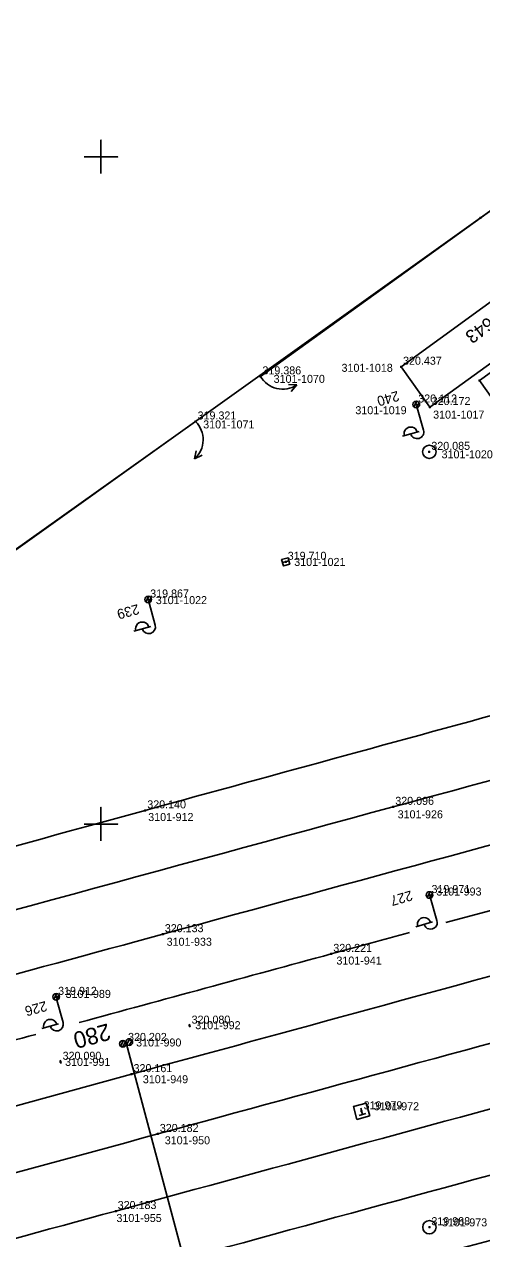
# Model space of a CAD drawing. Extents: x -821875 to -821475, y -1070280 to -1069975.
# Drawn here: x -821655.7 to -821621.5, y -1070181.1 to -1070090.1 of the extents above; entities that cross this region are included whole.
import ezdxf

# ---------------------------------------------------------------- set-up
doc = ezdxf.new("R2010")
doc.units = 0
for name, color, linetype in [('Vrstva 1', 7, 'Continuous'), ('Vrstva 11', 7, 'Continuous'), ('Vrstva 17', 7, 'Continuous'), ('Vrstva 20', 7, 'Continuous'), ('Vrstva 23', 7, 'Continuous'), ('Vrstva 25', 7, 'Continuous'), ('Vrstva 3', 7, 'Continuous'), ('Vrstva 33', 7, 'Continuous'), ('Vrstva 36', 7, 'Continuous'), ('Vrstva 43', 7, 'Continuous'), ('Vrstva 52', 7, 'Continuous'), ('Vrstva 53', 7, 'Continuous'), ('Vrstva 57', 7, 'Continuous'), ('Vrstva 60', 7, 'Continuous'), ('Vrstva 61', 7, 'Continuous')]:
    doc.layers.add(name, color=color, linetype=linetype)

# ---------------------------------------------------------------- blocks, each defined once
blk = doc.blocks.new('BOD')
at = {"layer": 'Vrstva 3'}
for p, q in [((-0.15, 0), (0.15, 0)), ((0, -0.15), (0, 0.15))]:
    blk.add_line(p, q, dxfattribs=at)

msp = doc.modelspace()

# ---------------------------------------------------------------- linework, layer by layer
at = {"layer": 'Vrstva 1'}
msp.add_line((-821601.389, -1070151.191), (-821624.154, -1070157.393), dxfattribs=at)
for points in [[(-821651.25, -1070100), (-821650, -1070100), (-821650, -1070098.75), (-821650, -1070100), (-821648.75, -1070100), (-821650, -1070100), (-821650, -1070101.25)], [(-821651.25, -1070150), (-821650, -1070150), (-821650, -1070148.75), (-821650, -1070150), (-821648.75, -1070150), (-821650, -1070150), (-821650, -1070151.25)], [(-821647.71, -1070168.745), (-821689.454, -1070180.207)]]:
    msp.add_lwpolyline(points, dxfattribs=at)
for points in [[(-821515.135, -1070116.801), (-821528.933, -1070119.148), (-821545.007, -1070122.191), (-821565.452, -1070126.847), (-821593.911, -1070134.524), (-821616.729, -1070140.773), (-821646.681, -1070148.977), (-821681.98, -1070158.691), (-821694.065, -1070162.076), (-821706.535, -1070165.88), (-821718.507, -1070169.937)], [(-821540.596, -1070125.428), (-821552.18, -1070128.307), (-821562.458, -1070130.974), (-821571.2, -1070133.262), (-821591.887, -1070138.848), (-821628.102, -1070148.713), (-821679.285, -1070162.663)], [(-821540.784, -1070127.42), (-821561.358, -1070134.748), (-821573.215, -1070138.464), (-821586.824, -1070142.326), (-821602.341, -1070146.553), (-821645.37, -1070158.257), (-821677.113, -1070166.912)], [(-821500, -1070129.211), (-821517.764, -1070133.43), (-821543.081, -1070140.233), (-821582.867, -1070151.05), (-821612.032, -1070158.997), (-821647.71, -1070168.745)], [(-821500, -1070134.157), (-821525.227, -1070140.424), (-821545.665, -1070145.962), (-821584.89, -1070156.649), (-821608.863, -1070163.173), (-821645.742, -1070173.228), (-821684.141, -1070183.689)], [(-821500, -1070139.002), (-821505.719, -1070140.359), (-821526.796, -1070145.75), (-821547.362, -1070151.333), (-821583.687, -1070161.245), (-821611.332, -1070168.765), (-821648.899, -1070179.006), (-821680.4, -1070187.609), (-821711.133, -1070195.974)], [(-821500, -1070143.947), (-821500.602, -1070144.082), (-821526.98, -1070150.62), (-821544.477, -1070155.432), (-821558.026, -1070159.151), (-821579.135, -1070164.951), (-821610.376, -1070173.463), (-821647.463, -1070183.595), (-821678.921, -1070192.191), (-821710.276, -1070200.761)], [(-821500, -1070148.817), (-821511.77, -1070151.622), (-821530.609, -1070156.564), (-821556.604, -1070163.701), (-821576.895, -1070169.217), (-821607.294, -1070177.525), (-821643.435, -1070187.343), (-821669.656, -1070194.488)], [(-821626.879, -1070158.135), (-821632.745, -1070159.733), (-821651.624, -1070164.877)], [(-821654.889, -1070165.767), (-821663.065, -1070167.996), (-821679.008, -1070172.349)]]:
    msp.add_spline(points, degree=3, dxfattribs=at)
at = {"layer": 'Vrstva 11'}
for p, q in [((-821648.314, -1070166.228), (-821648.548, -1070166.639)), ((-821648.157, -1070166.332), (-821648.379, -1070166.721)), ((-821648.122, -1070166.406), (-821638.674, -1070201.687)), ((-821647.829, -1070166.097), (-821648.065, -1070166.509)), ((-821647.673, -1070166.201), (-821647.894, -1070166.589))]:
    msp.add_line(p, q, dxfattribs=at)
for centre in [(-821648.363, -1070166.472), (-821648.363, -1070166.472), (-821647.881, -1070166.34), (-821647.881, -1070166.34)]:
    msp.add_circle(centre, 0.25, dxfattribs=at)
at = {"layer": 'Vrstva 17'}
for points in [[(-821638.053, -1070116.453), (-821603.288, -1070091.399)], [(-821785.347, -1070191.975), (-821782.414, -1070181.46), (-821781.172, -1070177.336), (-821779.748, -1070173.57), (-821777.608, -1070170.061), (-821774.963, -1070166.997), (-821771.94, -1070164.191), (-821768.526, -1070161.97), (-821763.149, -1070159.284), (-821721.814, -1070148.42), (-821694.32, -1070141.229), (-821660.419, -1070132.27), (-821642.912, -1070119.833)]]:
    msp.add_lwpolyline(points, dxfattribs=at)
at = {"layer": 'Vrstva 20'}
msp.add_lwpolyline([(-821621.64, -1070116.774), (-821619.812, -1070119.329), (-821614.129, -1070115.247), (-821615.939, -1070112.668), (-821621.64, -1070116.774)], dxfattribs=at)
at = {"layer": 'Vrstva 23'}
for p, q in [((-821635.335, -1070117.095), (-821635.944, -1070117.052)), ((-821635.746, -1070117.575), (-821635.335, -1070117.095)), ((-821635.335, -1070117.095), (-821635.746, -1070117.575)), ((-821642.988, -1070122.626), (-821642.873, -1070122.026)), ((-821642.418, -1070122.351), (-821642.988, -1070122.626)), ((-821642.988, -1070122.626), (-821642.418, -1070122.351))]:
    msp.add_line(p, q, dxfattribs=at)
msp.add_lwpolyline([(-821627.52, -1070115.73), (-821618.47, -1070109.17), (-821616.3, -1070112.22), (-821625.37, -1070118.75), (-821627.52, -1070115.73)], dxfattribs=at)
for centre, start, end in [((-821636.392, -1070115.496), 209.9472, 303.46708), ((-821644.263, -1070121.193), 311.68479, 45.20467)]:
    msp.add_arc(centre, 1.917, start, end, dxfattribs=at)
at = {"layer": 'Vrstva 25'}
for p, q in [((-821626.325, -1070118.317), (-821626.557, -1070118.736)), ((-821626.171, -1070118.424), (-821626.384, -1070118.809)), ((-821626.311, -1070118.801), (-821625.83, -1070120.483)), ((-821626.166, -1070120.58), (-821627.417, -1070120.937)), ((-821646.405, -1070132.933), (-821646.643, -1070133.348)), ((-821646.252, -1070133.042), (-821646.47, -1070133.423)), ((-821646.398, -1070133.416), (-821645.94, -1070135.105)), ((-821646.278, -1070135.197), (-821647.532, -1070135.537)), ((-821625.331, -1070155.079), (-821625.562, -1070155.498)), ((-821625.176, -1070155.186), (-821625.388, -1070155.57)), ((-821625.316, -1070155.562), (-821624.831, -1070157.243)), ((-821625.167, -1070157.34), (-821626.416, -1070157.701)), ((-821653.304, -1070162.711), (-821653.542, -1070163.127)), ((-821653.15, -1070162.819), (-821653.369, -1070163.202)), ((-821653.296, -1070163.194), (-821652.836, -1070164.883)), ((-821653.173, -1070164.975), (-821654.428, -1070165.317))]:
    msp.add_line(p, q, dxfattribs=at)
for centre in [(-821626.38, -1070118.56), (-821626.38, -1070118.56), (-821646.463, -1070133.175), (-821646.463, -1070133.175), (-821625.385, -1070155.322), (-821625.385, -1070155.322), (-821653.362, -1070162.953), (-821653.362, -1070162.953)]:
    msp.add_circle(centre, 0.25, dxfattribs=at)
for centre, start, end in [((-821626.793, -1070120.752), 15.25749, 196.66264), ((-821626.311, -1070120.62), 195.96007, 15.96007), ((-821646.906, -1070135.361), 14.46508, 195.87022), ((-821646.422, -1070135.236), 195.16765, 15.16765), ((-821625.793, -1070157.515), 15.38101, 196.78616), ((-821625.311, -1070157.382), 196.08359, 16.08359), ((-821653.802, -1070165.14), 14.54453, 195.94968), ((-821653.318, -1070165.014), 195.24711, 15.24711)]:
    msp.add_arc(centre, 0.5, start, end, dxfattribs=at)
at = {"layer": 'Vrstva 33'}
for p, q in [((-821630.167, -1070171.706), (-821630.65, -1070171.837)), ((-821630.408, -1070171.772), (-821630.54, -1070171.288))]:
    msp.add_line(p, q, dxfattribs=at)
msp.add_lwpolyline([(-821629.86, -1070171.882), (-821630.826, -1070172.144), (-821631.088, -1070171.178), (-821630.122, -1070170.916), (-821629.86, -1070171.882)], dxfattribs=at)
at = {"layer": 'Vrstva 36'}
for p, q in [((-821643.329, -1070165.233), (-821643.394, -1070164.992)), ((-821652.991, -1070167.94), (-821653.058, -1070167.699))]:
    msp.add_line(p, q, dxfattribs=at)
at = {"layer": 'Vrstva 43'}
msp.add_lwpolyline([(-821635.92, -1070130.28), (-821635.854, -1070130.521), (-821636.335, -1070130.654), (-821636.468, -1070130.173), (-821635.987, -1070130.04), (-821635.92, -1070130.28), (-821636.402, -1070130.414)], dxfattribs=at)
for centre in [(-821625.401, -1070122.108), (-821625.397, -1070180.216)]:
    msp.add_circle(centre, 0.5, dxfattribs=at)
at = {"layer": 'Vrstva 52'}
msp.add_lwpolyline([(-821627.52, -1070115.73), (-821618.47, -1070109.17), (-821616.3, -1070112.22), (-821625.37, -1070118.75), (-821627.52, -1070115.73)], dxfattribs=at)
at = {"layer": 'Vrstva 53'}
msp.add_lwpolyline([(-821734.56, -1070151.86), (-821659.89, -1070131.96), (-821621.57, -1070104.56), (-821609.88, -1070096.2), (-821593.26, -1070084.26), (-821583.18, -1070077.05), (-821575.55, -1070071.56), (-821563.91, -1070063.18), (-821553.98, -1070056.16), (-821553.05, -1070055.49), (-821551.21, -1070054.16)], dxfattribs=at)

# ---------------------------------------------------------------- block references
at = {"layer": 'Vrstva 60', "xscale": 0.5, "yscale": 0.5}
for p in [(-821621.57, -1070104.56), (-821627.52, -1070115.73), (-821638.053, -1070116.453), (-821621.64, -1070116.774), (-821626.38, -1070118.56), (-821625.37, -1070118.75), (-821642.912, -1070119.833), (-821625.401, -1070122.108), (-821636.161, -1070130.347), (-821646.463, -1070133.175), (-821646.681, -1070148.977), (-821628.102, -1070148.713), (-821625.385, -1070155.322), (-821645.37, -1070158.257), (-821632.745, -1070159.733), (-821653.362, -1070162.953), (-821643.362, -1070165.111), (-821648.122, -1070166.406), (-821653.025, -1070167.818), (-821647.71, -1070168.745), (-821630.474, -1070171.53), (-821645.742, -1070173.228), (-821648.899, -1070179.006), (-821625.397, -1070180.216)]:
    msp.add_blockref('BOD', p, dxfattribs=at)

# ---------------------------------------------------------------- texts
at = {"layer": 'Vrstva 11'}
msp.add_text('280', height=1.25, rotation=195.30297, dxfattribs=at).set_placement((-821649.49, -1070164.925))
at = {"layer": 'Vrstva 25'}
for s, rotation, p in [('240', 195.96009, (-821627.783, -1070117.532)), ('239', 195.16777, (-821647.252, -1070133.516)), ('227', 196.08371, (-821626.785, -1070154.972)), ('226', 195.24712, (-821654.157, -1070163.261))]:
    msp.add_text(s, height=0.75, rotation=rotation, dxfattribs=at).set_placement(p)
at = {"layer": 'Vrstva 57'}
msp.add_text('5643', height=1, rotation=215.69159, dxfattribs=at).set_placement((-821620.383, -1070111.511))
at = {"layer": 'Vrstva 60'}
for s, p in [('3101-1070', (-821637.065, -1070116.938)), ('3101-1018', (-821631.977, -1070116.111)), ('3101-1019', (-821630.941, -1070119.289)), ('3101-1017', (-821625.116, -1070119.618)), ('3101-1071', (-821642.343, -1070120.353)), ('3101-1020', (-821624.483, -1070122.593)), ('3101-1021', (-821635.522, -1070130.658)), ('3101-1022', (-821645.894, -1070133.521)), ('3101-926', (-821627.775, -1070149.574)), ('3101-912', (-821646.462, -1070149.776)), ('3101-993', (-821624.883, -1070155.361)), ('3101-933', (-821645.081, -1070159.125)), ('3101-941', (-821632.36, -1070160.535)), ('3101-989', (-821652.654, -1070163.032)), ('3101-992', (-821642.934, -1070165.376)), ('3101-990', (-821647.369, -1070166.671)), ('3101-991', (-821652.689, -1070168.129)), ('3101-949', (-821646.863, -1070169.427)), ('3101-972', (-821629.561, -1070171.452)), ('3101-950', (-821645.221, -1070174.003)), ('3101-955', (-821648.842, -1070179.827)), ('3101-973', (-821624.458, -1070180.156))]:
    msp.add_text(s, height=0.6, dxfattribs=at).set_placement(p)
at = {"layer": 'Vrstva 61'}
for s, p in [('320.437', (-821627.37, -1070115.58)), ('319.386', (-821637.903, -1070116.303)), ('320.112', (-821626.23, -1070118.41)), ('320.172', (-821625.22, -1070118.6)), ('319.321', (-821642.762, -1070119.683)), ('320.085', (-821625.251, -1070121.958)), ('319.710', (-821636.011, -1070130.197)), ('319.867', (-821646.313, -1070133.025)), ('320.140', (-821646.531, -1070148.827)), ('320.096', (-821627.952, -1070148.563)), ('319.971', (-821625.235, -1070155.172)), ('320.133', (-821645.22, -1070158.107)), ('320.221', (-821632.595, -1070159.583)), ('319.912', (-821653.212, -1070162.803)), ('320.080', (-821643.212, -1070164.961)), ('320.202', (-821647.972, -1070166.256)), ('320.090', (-821652.875, -1070167.668)), ('320.161', (-821647.56, -1070168.595)), ('319.979', (-821630.324, -1070171.38)), ('320.182', (-821645.592, -1070173.078)), ('320.183', (-821648.749, -1070178.856)), ('319.988', (-821625.247, -1070180.066))]:
    msp.add_text(s, height=0.6, dxfattribs=at).set_placement(p)

doc.saveas('drawing.dxf')
